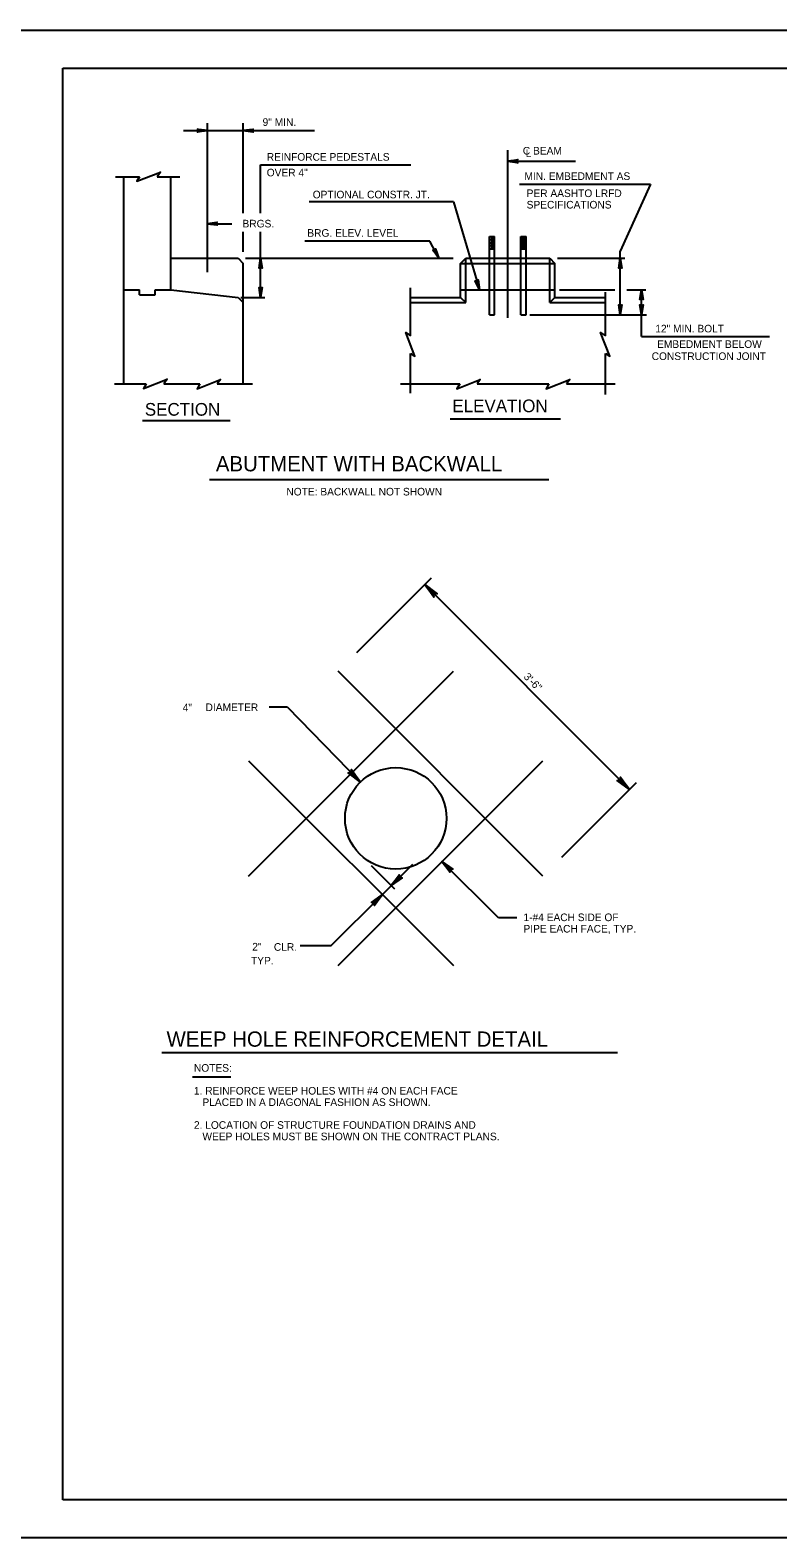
# Model space of a CAD drawing. Extents: x 235 to 2276, y 116 to 1308.
# Drawn here: x 1448 to 1742, y 710 to 1304 of the extents above; entities that cross this region are included whole.
import ezdxf

# ---------------------------------------------------------------- set-up
doc = ezdxf.new("R2010")
doc.units = 0
doc.layers.add('1', color=7, linetype='Continuous')
doc.layers.add('PLT-BNDY', color=7, linetype='Continuous')

msp = doc.modelspace()

# ---------------------------------------------------------------- linework, layer by layer
at = {"layer": '1'}
for p, q in [((1460.42, 725.41), (1460.42, 1289.41)), ((1460.42, 1289.41), (2246.42, 1289.41)), ((1517.36, 1209.1), (1517.36, 1267.71)), ((1531.44, 1232.33), (1531.44, 1267.71)), ((1507.95, 1264.83), (1559.47, 1264.83)), ((1635.69, 1191.02), (1635.69, 1257.15)), ((1538.31, 1251.4), (1597.39, 1251.4)), ((1538.31, 1232.33), (1538.31, 1251.4)), ((1635.69, 1252.77), (1662.31, 1252.77)), ((1481.19, 1246.65), (1490.56, 1246.65)), ((1484.44, 1165.02), (1484.44, 1246.65)), ((1497.56, 1246.65), (1506.44, 1246.65)), ((1502.94, 1202.15), (1502.94, 1246.65)), ((1640.31, 1243.77), (1691.81, 1243.77)), ((1691.81, 1243.77), (1679.94, 1217.4)), ((1614.31, 1236.77), (1557.44, 1236.77)), ((1614.31, 1236.77), (1624.44, 1202.15)), ((1517.36, 1228.15), (1526.9, 1228.15)), ((1531.44, 1217.04), (1531.44, 1224.97)), ((1538.31, 1199.15), (1538.31, 1224.97)), ((1604.94, 1221.27), (1555.69, 1221.27)), ((1608.44, 1214.52), (1604.94, 1221.27)), ((1628.44, 1223.15), (1630.44, 1223.15)), ((1628.44, 1214.52), (1628.44, 1223.15)), ((1628.44, 1221.9), (1630.44, 1221.9)), ((1628.44, 1220.65), (1630.44, 1220.65)), ((1628.44, 1219.52), (1630.44, 1219.52)), ((1628.44, 1218.27), (1630.44, 1218.27)), ((1628.94, 1222.52), (1629.94, 1222.52)), ((1628.94, 1221.27), (1629.94, 1221.27)), ((1628.94, 1220.15), (1629.94, 1220.15)), ((1628.94, 1218.9), (1629.94, 1218.9)), ((1630.44, 1214.52), (1630.44, 1223.15)), ((1640.81, 1223.15), (1642.81, 1223.15)), ((1640.81, 1214.52), (1640.81, 1223.15)), ((1640.81, 1221.9), (1642.81, 1221.9)), ((1640.81, 1220.65), (1642.81, 1220.65)), ((1640.81, 1219.52), (1642.81, 1219.52)), ((1640.81, 1218.27), (1642.81, 1218.27)), ((1641.19, 1222.52), (1642.31, 1222.52)), ((1641.19, 1221.27), (1642.31, 1221.27)), ((1641.19, 1220.15), (1642.31, 1220.15)), ((1641.19, 1218.9), (1642.31, 1218.9)), ((1642.81, 1214.52), (1642.81, 1223.15)), ((1502.94, 1214.52), (1529.44, 1214.52)), ((1529.44, 1214.52), (1531.44, 1212.52)), ((1531.44, 1165.02), (1531.44, 1212.52)), ((1532.31, 1214.52), (1614.06, 1214.52)), ((1533.06, 1214.52), (1543.94, 1214.52)), ((1617.06, 1212.52), (1619.06, 1214.52)), ((1617.06, 1199.15), (1617.06, 1212.52)), ((1617.06, 1212.52), (1654.19, 1212.52)), ((1619.06, 1214.52), (1652.19, 1214.52)), ((1619.06, 1197.15), (1619.06, 1214.52)), ((1628.44, 1192.27), (1628.44, 1214.52)), ((1630.44, 1192.27), (1630.44, 1214.52)), ((1640.81, 1192.27), (1640.81, 1214.52)), ((1642.81, 1192.27), (1642.81, 1214.52)), ((1652.19, 1197.15), (1652.19, 1214.52)), ((1652.19, 1214.52), (1654.19, 1212.52)), ((1654.19, 1199.15), (1654.19, 1212.52)), ((1655.19, 1214.52), (1681.69, 1214.52)), ((1679.94, 1192.27), (1679.94, 1217.4)), ((1484.44, 1202.15), (1490.56, 1202.15)), ((1490.56, 1200.15), (1490.56, 1202.15)), ((1490.56, 1200.15), (1496.81, 1200.15)), ((1496.81, 1200.15), (1496.81, 1202.15)), ((1496.81, 1202.15), (1502.94, 1202.15)), ((1502.94, 1202.15), (1529.44, 1199.15)), ((1597.31, 1184.02), (1597.31, 1202.9)), ((1617.06, 1202.15), (1654.19, 1202.15)), ((1656.06, 1202.15), (1677.75, 1202.15)), ((1674.06, 1184.02), (1674.06, 1201.15)), ((1682.52, 1202.15), (1690.06, 1202.15)), ((1688.31, 1183.77), (1688.31, 1202.15)), ((1529.44, 1199.15), (1531.44, 1197.15)), ((1530.56, 1199.15), (1539.94, 1199.15)), ((1597.31, 1199.15), (1617.06, 1199.15)), ((1597.31, 1197.15), (1619.06, 1197.15)), ((1617.06, 1199.15), (1619.06, 1197.15)), ((1654.19, 1199.15), (1652.19, 1197.15)), ((1652.19, 1197.15), (1674.06, 1197.15)), ((1654.19, 1199.15), (1674.06, 1199.15)), ((1628.44, 1192.27), (1630.44, 1192.27)), ((1640.81, 1192.27), (1642.81, 1192.27)), ((1644.31, 1192.27), (1690.31, 1192.27)), ((1688.31, 1183.77), (1738.75, 1183.77)), ((1597.31, 1161.4), (1597.31, 1177.02)), ((1674.06, 1160.9), (1674.06, 1177.02)), ((1480.81, 1165.02), (1493.19, 1165.02)), ((1500.19, 1165.02), (1514.31, 1165.02)), ((1521.19, 1165.02), (1535.06, 1165.02)), ((1593.44, 1165.02), (1616.69, 1165.02)), ((1623.56, 1165.02), (1651.81, 1165.02)), ((1658.81, 1165.02), (1677.94, 1165.02)), ((1491.83, 1150.65), (1526.36, 1150.65)), ((1612.99, 1151.27), (1656.38, 1151.27)), ((1518.17, 1127.32), (1651.8, 1127.32)), ((1605.52, 1088.56), (1576.1, 1059.14)), ((1683.6, 1005.27), (1602.91, 1085.95)), ((1533.55, 971.15), (1614.24, 1051.83)), ((1649.48, 971.15), (1568.8, 1051.83)), ((1548.91, 1037.73), (1541.61, 1037.73)), ((1548.91, 1037.73), (1577.59, 1008.2)), ((1533.55, 1016.59), (1614.24, 935.91)), ((1568.8, 935.91), (1649.48, 1016.59)), ((1686.21, 1007.88), (1656.78, 978.45)), ((1591.11, 966.01), (1581.92, 975.2)), ((1594.29, 971.9), (1598.26, 975.87)), ((1631.95, 954.66), (1609.69, 976.93)), ((1586.26, 963.88), (1594.29, 971.9)), ((1565.99, 943.6), (1586.26, 963.88)), ((1639.25, 954.66), (1631.95, 954.66)), ((1565.99, 943.6), (1553.93, 943.6)), ((1499.39, 901.66), (1678.85, 901.66)), ((1511.49, 892.07), (1526.62, 892.07)), ((2246.42, 725.41), (1460.42, 725.41))]:
    msp.add_line(p, q, dxfattribs=at)
for points in [[(1513.7, 1265.32), (1513.83, 1265.07), (1517.45, 1264.82), (1513.7, 1265.32), (1513.45, 1265.44), (1517.45, 1264.82), (1513.83, 1264.69), (1513.7, 1264.44), (1517.45, 1264.82), (1513.45, 1264.19), (1513.7, 1264.44)], [(1535.19, 1264.33), (1535.06, 1264.58), (1531.44, 1264.83), (1535.19, 1264.33), (1535.31, 1264.21), (1531.44, 1264.83), (1535.06, 1264.96), (1535.19, 1265.33), (1531.44, 1264.83), (1535.31, 1265.46), (1535.19, 1265.33)], [(1639.38, 1252.31), (1639.24, 1252.58), (1635.69, 1252.77), (1639.38, 1252.31), (1639.57, 1252.15), (1635.69, 1252.77), (1639.24, 1252.95), (1639.37, 1253.21), (1635.69, 1252.77), (1639.57, 1253.39), (1639.37, 1253.21)], [(1490.56, 1246.65), (1489.56, 1244.9), (1498.81, 1248.52), (1497.56, 1246.65)], [(1521.1, 1227.66), (1520.97, 1227.91), (1517.35, 1228.16), (1521.1, 1227.66), (1521.22, 1227.54), (1517.35, 1228.16), (1520.97, 1228.29), (1521.1, 1228.66), (1517.35, 1228.16), (1521.22, 1228.79), (1521.1, 1228.66)], [(1607.15, 1218.01), (1606.98, 1217.77), (1608.44, 1214.52), (1607.15, 1218.01), (1607.21, 1218.25), (1608.44, 1214.52), (1606.65, 1217.59), (1606.35, 1217.59), (1608.44, 1214.52), (1606.11, 1217.68), (1606.35, 1217.59)], [(1537.85, 1210.83), (1538.12, 1210.97), (1538.31, 1214.52), (1537.85, 1210.83), (1537.69, 1210.64), (1538.31, 1214.52), (1538.49, 1210.97), (1538.75, 1210.84), (1538.31, 1214.52), (1538.93, 1210.64), (1538.75, 1210.84)], [(1679.48, 1210.83), (1679.74, 1210.97), (1679.94, 1214.52), (1679.48, 1210.83), (1679.31, 1210.64), (1679.94, 1214.52), (1680.12, 1210.97), (1680.38, 1210.84), (1679.94, 1214.52), (1680.56, 1210.64), (1680.38, 1210.84)], [(1623.85, 1205.82), (1623.63, 1205.61), (1624.44, 1202.15), (1623.85, 1205.82), (1623.95, 1206.05), (1624.44, 1202.15), (1623.27, 1205.51), (1622.98, 1205.56), (1624.44, 1202.15), (1622.76, 1205.7), (1622.98, 1205.56)], [(1538.78, 1202.84), (1538.51, 1202.7), (1538.31, 1199.15), (1538.78, 1202.84), (1538.94, 1203.03), (1538.31, 1199.15), (1538.14, 1202.7), (1537.87, 1202.83), (1538.31, 1199.15), (1537.7, 1203.03), (1537.87, 1202.83)], [(1687.85, 1198.46), (1688.12, 1198.59), (1688.31, 1202.15), (1687.85, 1198.46), (1687.69, 1198.27), (1688.31, 1202.15), (1688.49, 1198.6), (1688.75, 1198.47), (1688.31, 1202.15), (1688.93, 1198.27), (1688.75, 1198.47)], [(1680.4, 1195.96), (1680.14, 1195.83), (1679.94, 1192.27), (1680.4, 1195.96), (1680.57, 1196.15), (1679.94, 1192.27), (1679.76, 1195.82), (1679.5, 1195.95), (1679.94, 1192.27), (1679.32, 1196.15), (1679.5, 1195.95)], [(1688.78, 1195.96), (1688.51, 1195.83), (1688.31, 1192.27), (1688.78, 1195.96), (1688.94, 1196.15), (1688.31, 1192.27), (1688.14, 1195.82), (1687.87, 1195.95), (1688.31, 1192.27), (1687.7, 1196.15), (1687.87, 1195.95)], [(1597.31, 1177.02), (1599.06, 1176.02), (1595.44, 1185.27), (1597.31, 1184.02)], [(1674.06, 1177.02), (1675.81, 1176.02), (1672.19, 1185.27), (1674.06, 1184.02)], [(1493.19, 1165.02), (1492.19, 1163.27), (1501.44, 1166.9), (1500.19, 1165.02)], [(1514.31, 1165.02), (1513.31, 1163.15), (1522.56, 1166.77), (1521.19, 1165.02)], [(1616.69, 1165.02), (1615.56, 1163.15), (1624.81, 1166.77), (1623.56, 1165.02)], [(1651.81, 1165.02), (1650.81, 1163.15), (1660.06, 1166.77), (1658.81, 1165.02)], [(1606.42, 1081.43), (1606.56, 1081.87), (1602.91, 1085.95), (1606.42, 1081.43), (1606.45, 1081.05), (1602.91, 1085.95), (1606.97, 1082.28), (1607.39, 1082.43), (1602.91, 1085.95), (1607.8, 1082.4), (1607.39, 1082.43)], [(1574.15, 1012.77), (1574, 1012.33), (1577.59, 1008.2), (1574.15, 1012.77), (1574.12, 1013.16), (1577.59, 1008.2), (1573.59, 1011.93), (1573.16, 1011.79), (1577.59, 1008.2), (1572.75, 1011.82), (1573.16, 1011.79)], [(1680.09, 1009.78), (1679.95, 1009.34), (1683.6, 1005.27), (1680.09, 1009.78), (1680.06, 1010.17), (1683.6, 1005.27), (1679.54, 1008.94), (1679.12, 1008.79), (1683.6, 1005.27), (1678.71, 1008.81), (1679.12, 1008.79)], [(1612.78, 972.95), (1612.9, 973.34), (1609.69, 976.93), (1612.78, 972.95), (1612.8, 972.62), (1609.69, 976.93), (1613.25, 973.7), (1613.63, 973.83), (1609.69, 976.93), (1613.99, 973.81), (1613.63, 973.83)], [(1593.73, 970.45), (1593.34, 970.58), (1589.75, 967.37), (1593.73, 970.45), (1594.06, 970.48), (1589.75, 967.37), (1592.98, 970.93), (1592.85, 971.31), (1589.75, 967.37), (1592.88, 971.67), (1592.85, 971.31)], [(1582.29, 960.79), (1582.68, 960.67), (1586.26, 963.88), (1582.29, 960.79), (1581.95, 960.76), (1586.26, 963.88), (1583.04, 960.31), (1583.16, 959.94), (1586.26, 963.88), (1583.14, 959.57), (1583.16, 959.94)]]:
    msp.add_lwpolyline(points, dxfattribs=at)
msp.add_circle((1591.52, 993.87), 19.99, dxfattribs=at)
at = {"layer": 'PLT-BNDY'}
msp.add_lwpolyline([(1420.42, 1304.41), (2261.42, 1304.41), (2261.42, 710.41), (1420.42, 710.41)], close=True, dxfattribs=at)

# ---------------------------------------------------------------- texts
at = {"layer": '1'}
for s, height, p in [('9" MIN.', 3.003, (1539.07, 1266.69)), ('REINFORCE PEDESTALS', 3, (1540.71, 1252.99)), ('C BEAM', 3, (1641.56, 1255.4)), ('L', 3, (1642.69, 1254.4)), ('OVER 4"', 3, (1540.71, 1246.81)), ('MIN. EMBEDMENT AS', 3, (1642.19, 1245.4)), ('PER AASHTO LRFD', 3, (1643.06, 1238.65)), ('OPTIONAL CONSTR. JT.', 3, (1558.81, 1238.15)), ('SPECIFICATIONS', 3, (1643.06, 1234.15)), ('  BRGS.', 3, (1528.92, 1226.69)), ('BRG. ELEV. LEVEL', 3, (1556.69, 1223.02)), ('EMBEDMENT BELOW', 3, (1694.43, 1179.21)), (' CONSTRUCTION JOINT', 3, (1691.18, 1174.46)), ('ELEVATION', 5, (1613.81, 1153.9)), ('SECTION', 5, (1492.69, 1152.52)), ('ABUTMENT WITH BACKWALL', 6, (1520.67, 1130.6)), ('NOTE: BACKWALL NOT SHOWN', 3, (1548.44, 1121.09)), ('4"', 3.003, (1507.6, 1036.01)), ('DIAMETER', 3, (1516.62, 1036.15)), ('1-#4 EACH SIDE OF', 3, (1641.81, 953.39)), ('PIPE EACH FACE, TYP.', 3, (1641.81, 948.89)), ('2"', 3.003, (1535, 941.81)), ('CLR.', 3, (1543.52, 941.71)), ('TYP.', 3, (1534.51, 936.32)), ('WEEP HOLE REINFORCEMENT DETAIL', 6, (1501.26, 903.92)), ('NOTES:', 3, (1512.03, 894.06)), ('1. REINFORCE WEEP HOLES WITH #4 ON EACH FACE', 3, (1512.03, 885.06)), ('   PLACED IN A DIAGONAL FASHION AS SHOWN.', 3, (1512.03, 880.56)), ('2. LOCATION OF STRUCTURE FOUNDATION DRAINS AND', 3, (1512.03, 871.56)), ('   WEEP HOLES MUST BE SHOWN ON THE CONTRACT PLANS.', 3, (1512.03, 867.06))]:
    msp.add_text(s, height=height, dxfattribs=at).set_placement(p)
for s, rotation, p in [('12" MIN. BOLT', 360, (1693.73, 1185.34)), ('3\'-6"', 315, (1641.66, 1049.42))]:
    msp.add_text(s, height=3, rotation=rotation, dxfattribs=at).set_placement(p)

doc.saveas('drawing.dxf')
